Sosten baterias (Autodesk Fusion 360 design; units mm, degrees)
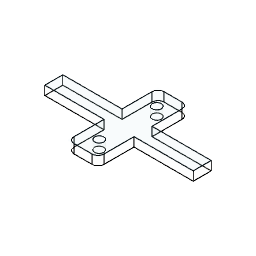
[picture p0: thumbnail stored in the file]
part number: 2026-07-18-00-36-21-007
sketch "Boceto1" plane through (0, 0, 0) normal (0, 0, 1) x axis (1, 0, 0)
  line L1 (0, 6) -> (0, 0)
  line L2 (49.5, 6) -> (0, 6)
  line L3 (49.5, 0) -> (49.5, 6)
  line L4 (0, 0) -> (49.5, 0)
  line L5 (25, 18) -> (25, 6)
  line L6 (30, 18) -> (25, 18)
  line L7 (30, -12) -> (30, 18)
  line L8 (20, -12) -> (30, -12)
  line L9 (20, 18) -> (20, -12)
  line L10 (25, 18) -> (20, 18)
  line L11 (25, 14.1) -> (25, 18)
  line L12 (25, 12.6) -> (25, 14.1)
  line L13 (25, -8.1) -> (25, -12)
  line L14 (25, -6.6) -> (25, -8.1)
  circle C1 centre (25, 12.6) radius 1.5
  circle C2 centre (25, -6.6) radius 1.5
  point P1 (0, 0)
  point P2 (0, 0)
  point P6 (25, 6)
  point P13 (25, 12.6)
  point P14 (25, 12.6)
  point P15 (25, -12)
  point P17 (25, -6.6)
  point P18 (25, -6.6)
  point P16 (25, -8.1)
  point P3 (0, 6)
  point P4 (49.5, 6)
  point P7 (25, 18)
  point P12 (25, 14.1)
  coincident P1 P2
  vertical L1
  perpendicular L1 L2
  perpendicular L2 L3
  perpendicular L1 L4
  coincident L2 P6
  perpendicular L2 L5
  perpendicular L5 L6
  perpendicular L2 L7
  perpendicular L7 L8
  perpendicular L4 L9
  perpendicular L5 L10
  perpendicular L6 L11
  parallel L5 L12
  coincident P13 P14
  midpoint L8 P15
  perpendicular L8 L13
  parallel L13 L14
  coincident P17 P18
  coincident P16 C2
  dimension "d1" distance P2 P3 = 6
  dimension "d2" distance P3 P4 = 49.5
  dimension "d3" distance P6 P7 = 12
  dimension "d4" distance P7 P12 = 3.9
  dimension "d5" distance P12 P13 = 1.5
  dimension "d6" diameter C1 = 3
  dimension "d7" distance P15 P16 = 3.9
  dimension "d8" distance P16 P17 = 1.5
extrude "Extruir1" new body sketch "Boceto1" profile of L1 L2 L3 L4 L5 L6 L7 L8 L9 L10 L11 C1 L13 C2 along normal blind 3
extrude "Extruir2" cut of existing geometry blind -0.25
extrude "Extruir3" add of existing geometry blind 0.25
sketch "Boceto2" plane through (0, 0, 3) normal (0, 0, 1) x axis (-1, 0, 0)
  line L1 (-0.25, 0) -> (-0.25, -6)
  line L2 (-20, 0) -> (-0.25, 0)
  line L3 (-20, 12) -> (-20, 0)
  line L4 (-30, 12) -> (-20, 12)
  line L5 (-30, 0) -> (-30, 12)
  line L6 (-49.75, 0) -> (-30, 0)
  line L7 (-49.75, -6) -> (-49.75, 0)
  line L8 (-30, -6) -> (-49.75, -6)
  line L9 (-30, -18) -> (-30, -6)
  line L10 (-20, -18) -> (-30, -18)
  line L11 (-20, -6) -> (-20, -18)
  line L12 (-0.25, -6) -> (-20, -6)
  circle C1 centre (-25, -12.6) radius 1.5
  circle C2 centre (-25, 6.6) radius 1.5
fillet "Empalme" radius 2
